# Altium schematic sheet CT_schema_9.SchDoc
size 390 x 278 mm
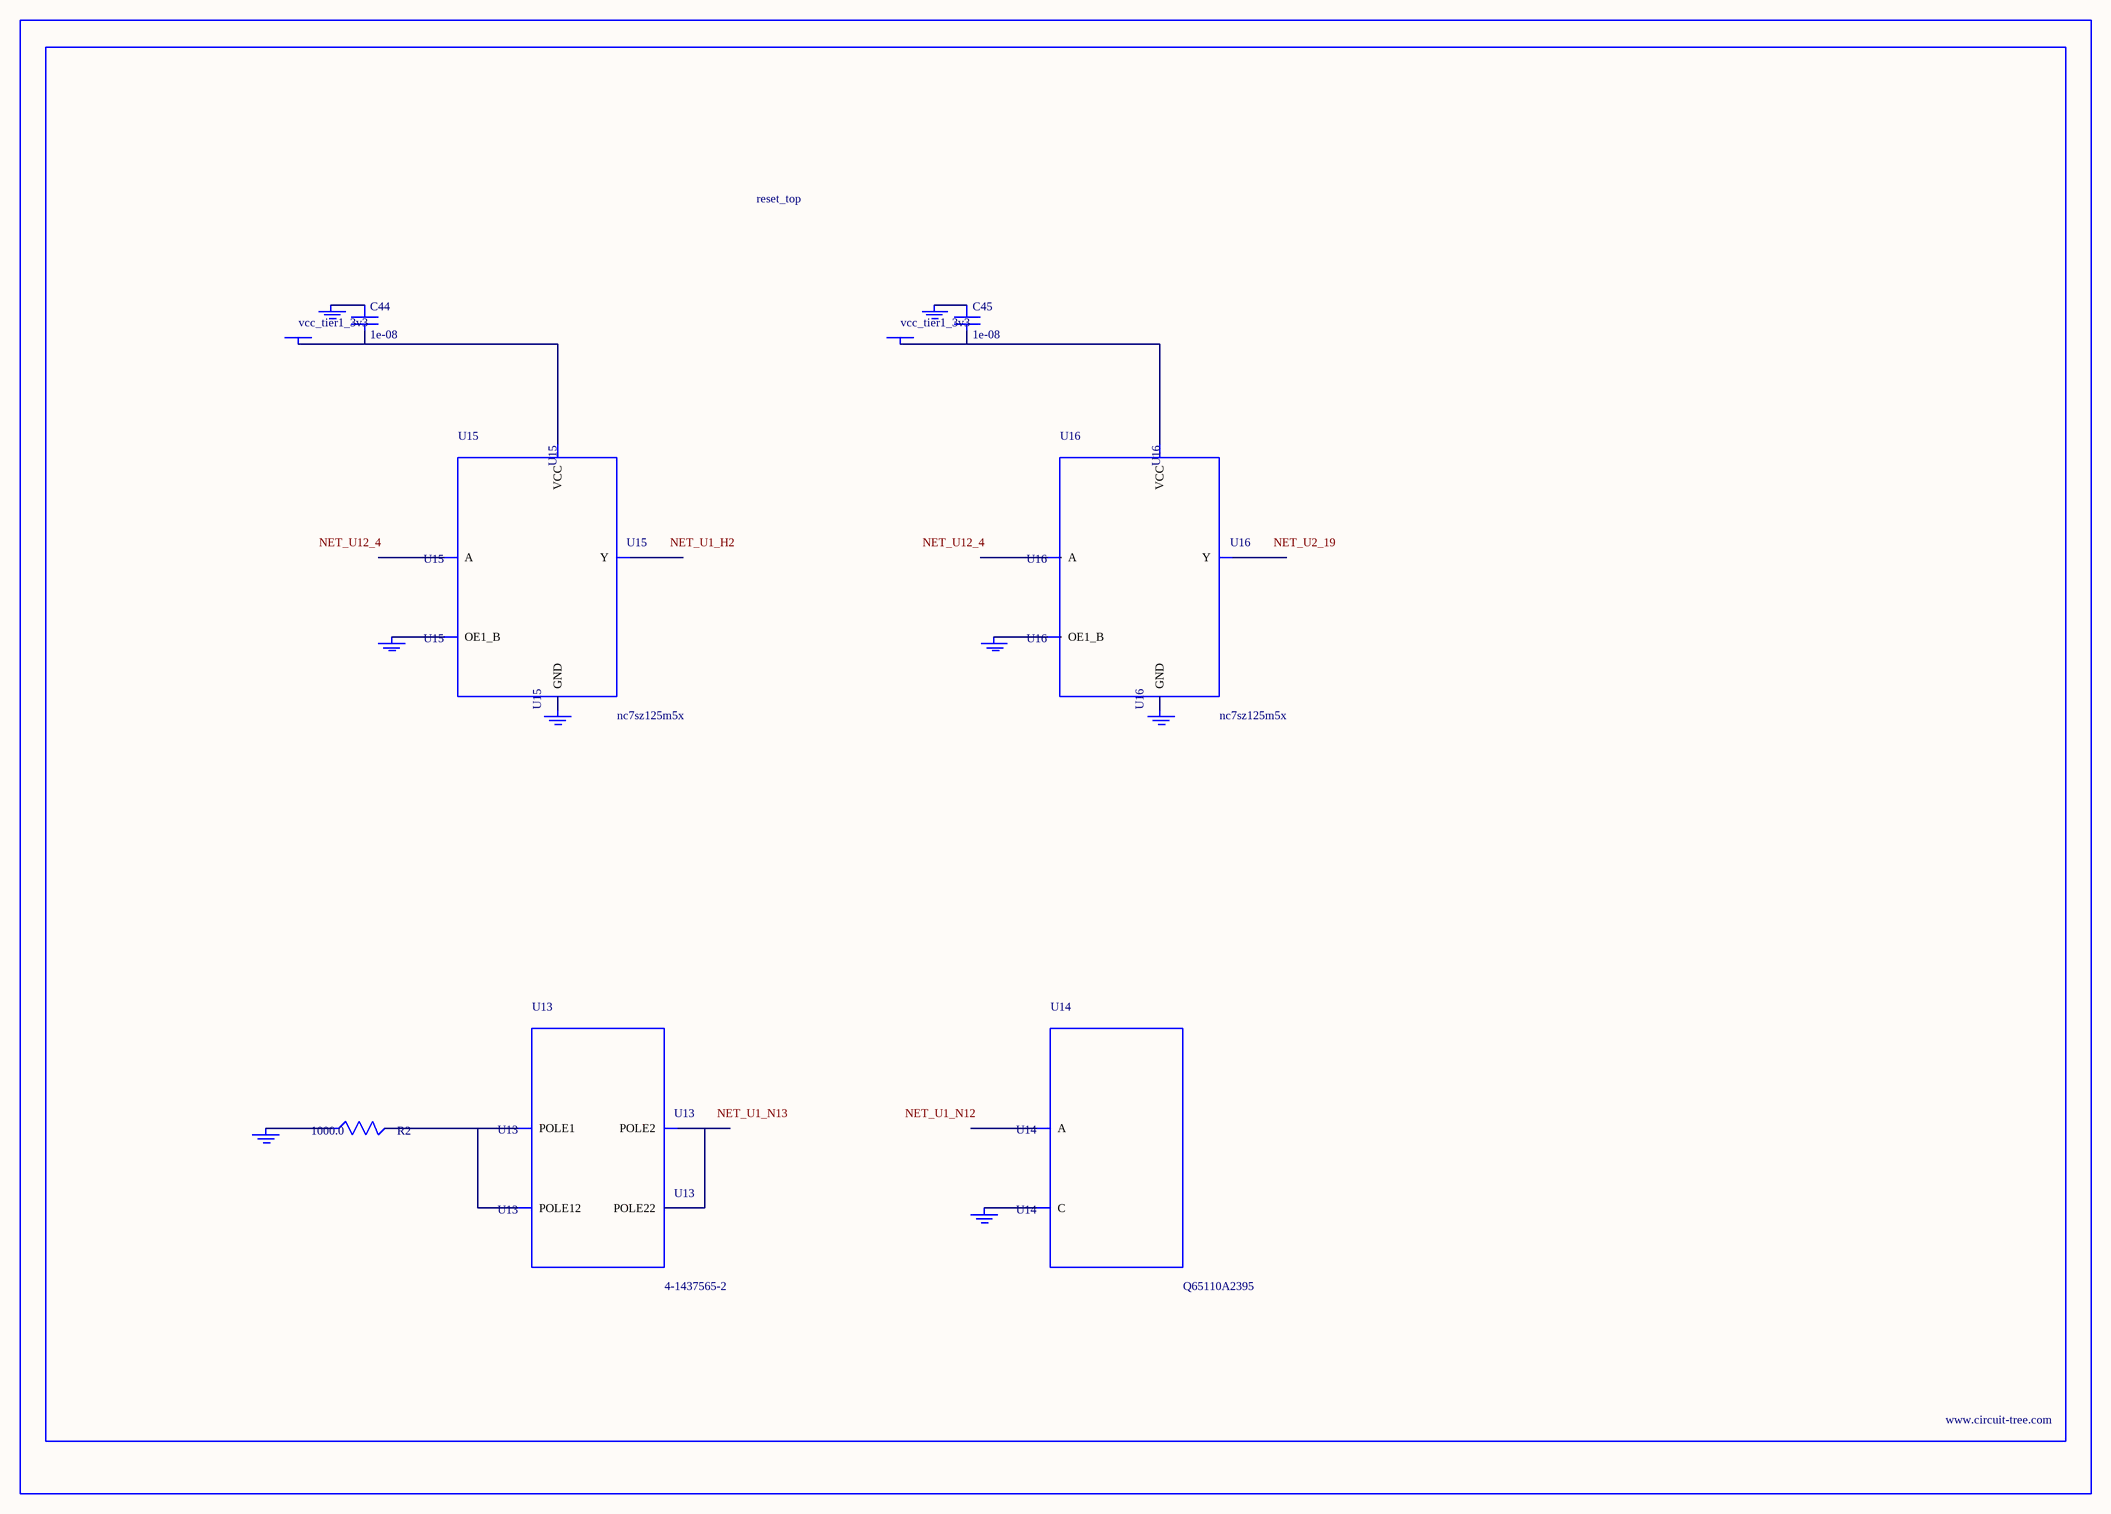
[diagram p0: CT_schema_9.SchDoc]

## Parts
BORDER8  (no value)
C44  1e-08  [C0402]
C45  1e-08  [C0402]
GND_INSTANCE_8_0  (no value)
GND_INSTANCE_8_1  (no value)
GND_INSTANCE_8_2  (no value)
GND_INSTANCE_8_3  (no value)
GND_INSTANCE_8_4  (no value)
GND_INSTANCE_8_5  (no value)
GND_INSTANCE_8_6  (no value)
GND_INSTANCE_8_7  (no value)
POWER_INSTANCE_8_0  vcc_tier1_3v3
POWER_INSTANCE_8_1  vcc_tier1_3v3
R2  1000.0  [R0603]
U13  4-1437565-2  [SW_4-1437565-2]
U14  Q65110A2395  [LGM67K-G1J2-24-Z]
U15  nc7sz125m5x  [NC7SZ125M5X]
U16  nc7sz125m5x  [NC7SZ125M5X]

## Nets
NetC44_1: C44.1 GND_INSTANCE_8_2.0(GND)
NetC44_2: C44.2 POWER_INSTANCE_8_0.0(PWR) U15.5(VCC)
NetC45_1: C45.1 GND_INSTANCE_8_5.0(GND)
NetC45_2: C45.2 POWER_INSTANCE_8_1.0(PWR) U16.5(VCC)
NetGND_INSTANCE_8_0_0: GND_INSTANCE_8_0.0(GND) R2.1
NetGND_INSTANCE_8_1_0: GND_INSTANCE_8_1.0(GND) U14.C
NetGND_INSTANCE_8_3_0: GND_INSTANCE_8_3.0(GND) U15.1(OE1_B)
NetGND_INSTANCE_8_4_0: GND_INSTANCE_8_4.0(GND) U15.3(GND)
NetGND_INSTANCE_8_6_0: GND_INSTANCE_8_6.0(GND) U16.1(OE1_B)
NetGND_INSTANCE_8_7_0: GND_INSTANCE_8_7.0(GND) U16.3(GND)
NetR2_2: R2.2 U13.1(POLE1) U13.2(POLE12)
NetU13_3: U13.3(POLE2) U13.4(POLE22)

Not connected (* = marked no-connect by the designer): U14 A; U15 2(A) 4(Y); U16 2(A) 4(Y)

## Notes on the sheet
- Labels drawn without touching a wire or pin: NET_U1_H2, NET_U1_N12, NET_U1_N13, NET_U2_19, NET_U12_4

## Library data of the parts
BORDER8 = BORDER_PAGE8
C44 C45 = C0402C103K3RAC
GND_INSTANCE_8_0-GND_INSTANCE_8_7 = GND
POWER_INSTANCE_8_0 POWER_INSTANCE_8_1 = PWR
R2 = RC0603JR-071KL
